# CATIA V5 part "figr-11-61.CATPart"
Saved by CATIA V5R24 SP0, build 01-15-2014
Part number: Part1
Bounding box of the stored display mesh (mm): x -54 to 54, y -91.936 to 93.838, z -12.649 to 110.643
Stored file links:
  D:\KAVITA\CATIA V5-6R2014 Project_ Kavita\CATIA V5-6R2014_partfiles\Partfiles\c11_catia_v5-6r2014_prt\figr-11-61.CATPart
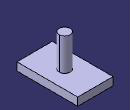
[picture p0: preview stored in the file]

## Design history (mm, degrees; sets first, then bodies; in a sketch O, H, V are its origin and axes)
Set1
  Loft1: Sections (Sketch4; Sketch3)
Body1 (main body)
  Sketch1 on yz-plane, origin (0, 0, 0), H (0, 1, 0), V (0, 0, 1)
    point P1 (93.8379, 11.643)
    line L1 (93.8379, 11.643) -> (93.8379, -12.6487)
    line L2 (93.8379, -12.6487) -> (-91.9362, -12.6487)
    line L3 (-91.9362, -12.6487) -> (-91.9362, 11.643)
    line L4 (-91.9362, 11.643) -> (93.8379, 11.643)
    point P5 (93.8379, 11.643)
    vertical: L1 V, L3 V
    horizontal: L2 H, L4 H
    coincidence: P5 P1
  Pad1: profile Sketch1, direction (1, 0, 0), length 54, mirrored extent
  Sketch2 on face of Pad1, origin (0, 0, 11.643), H (1, 0, 0), V (0, 1, 0)
    circle A1 centre (0, 0) radius 16.7533
    point P1 (16.7533, 0)
    coincidence: A1 P1, P1 H
  Pad2: profile Sketch2, direction (0, 0, 1), length 99
  Sketch3 on face of Pad2, origin (0, 0, 110.643), H (1, 0, 0), V (0, 1, 0)
    point P1 (0, 42.8937)
    point P2 (33.9651, 0)
    projected circle E1 centre (0, 0) radius 16.7533 from edge [face of Pad2 | face of Pad2]
    circle A1 centre (0, 0) radius 33.9651
    point P3 (0, 33.9651)
    coincidence: P1 V, P2 H, A1 P2, A1 P3, P3 V
  Sketch4 on face of Pad1, origin (0, 0, 11.643), H (1, 0, 0), V (0, 1, 0)
    ellipse A1 centre (0, 0) semi-axes 69.9141, 43.1918 rotation 90
    point P1 (0, 69.9141)
    point P2 (43.1918, 0)
    coincidence: P1 V, P2 H, A1 P1, A1 P2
